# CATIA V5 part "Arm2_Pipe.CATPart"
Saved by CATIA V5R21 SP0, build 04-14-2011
Part number: Arm2_Pipe
Bounding box of the stored display mesh (mm): x 0 to 180, y -12.5 to 12.5, z -12.409 to 12.409
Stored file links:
  C:\Users\水心\Desktop\arm\Arm_Detailed_Design\Arm2_Pipe.CATPart
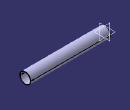
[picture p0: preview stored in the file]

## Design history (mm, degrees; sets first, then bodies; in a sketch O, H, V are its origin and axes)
Body1 (main body)
  Sketch1 on yz-plane, origin (0, 0, 0), H (0, 1, 0), V (0, 0, 1)
    circle A1 centre (0, 0) radius 11.5
    circle A2 centre (0, 0) radius 12.5
    radius A1 = 11.5
    radius A2 = 12.5
  Pad1: profile Sketch1, direction (1, 0, 0), length 180
  Sketch2 on zx-plane, origin (0, 0, 0), H (-1, 0, 0), V (0, 0, 1)
    circle A1 centre (-6, 0) radius 1.25
    point P1 (-6, 0)
    circle A2 centre (-174, 0) radius 1.25
    point P2 (-174, 0)
    reference projected line E1 (-180, -12.5) -> (-180, 12.5) from edge [face of Pad1 from Sketch1.A2 | end face of Pad1]
    radius A1 = 1.25
    distance V P1 = 6
    radius A2 = 1.25
    distance E1 P2 = 6
    coincidence: P1 H, P2 H
  Pocket1: profile Sketch2, direction (0, -1, 0), length 50, mirrored extent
